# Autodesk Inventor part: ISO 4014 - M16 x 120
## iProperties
Created: 2009-02
Part Number: ISO 4014 - M16 x 120
Material: Stainless Steel, 440C
Description: Hexagon head bolt - product grades A and B
Document SubType Name: Modeling
Standard: ISO 4014
Designer: 904Chiaki
Standard Revision: Third edition 1999-09-01
Standards Organization: ISO
Language: en-US
Size Designation: M16 x 120
Categories: <MemberInstance><Categories><Category DisplayName="Fasteners" InternalName="e4da775c-781d-43d5-af7c-5136215cf5a6" Mnemonic="FSTN"><Category DisplayName="Bolts"
Density: 7.75 g/cm^3
Mass: 224.623 g
Surface Area: 77.8946 cm^2
Volume: 28.9836 cm^3
IsCustomPart: 0
Author: 904Chiaki
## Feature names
1. Body [Revolution]
2. Head [Extrusion]
3. Chamfer1 [Revolution]
4. Chamfer2
